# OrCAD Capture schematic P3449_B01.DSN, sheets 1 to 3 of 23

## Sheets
1 0022_Mechanical: size Custom
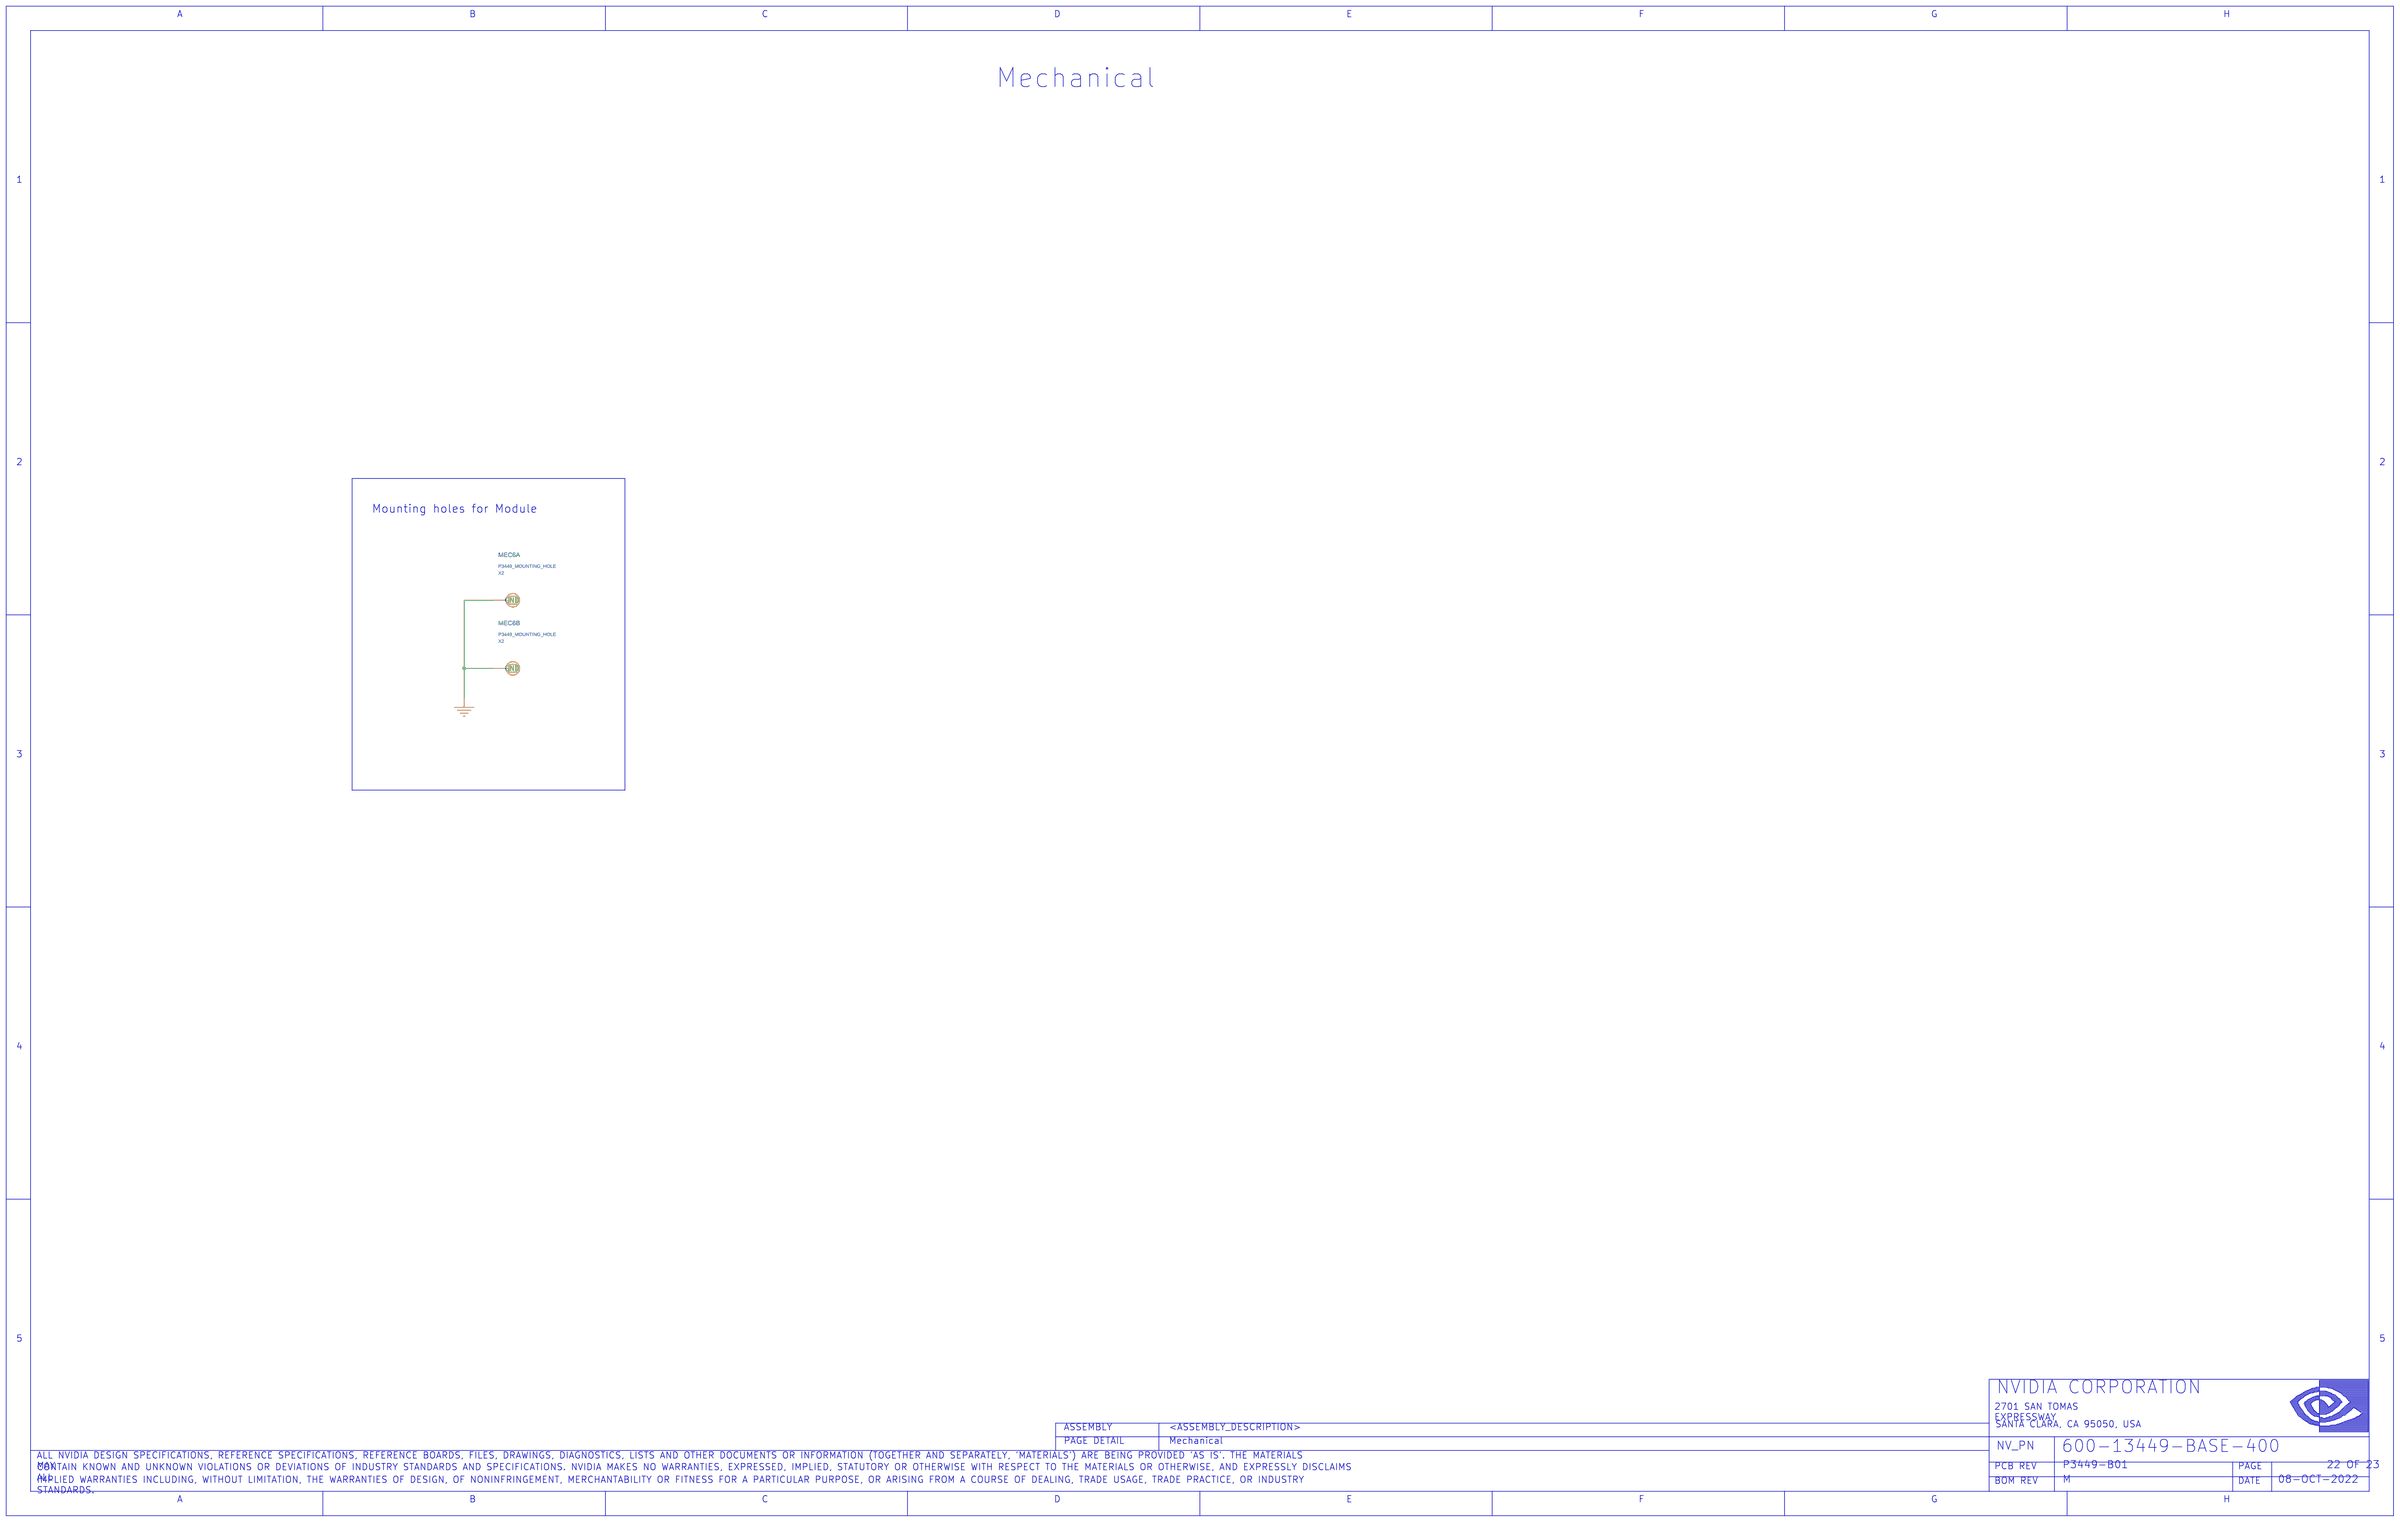
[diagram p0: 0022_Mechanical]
2 0021_Loop Back Test: size Custom
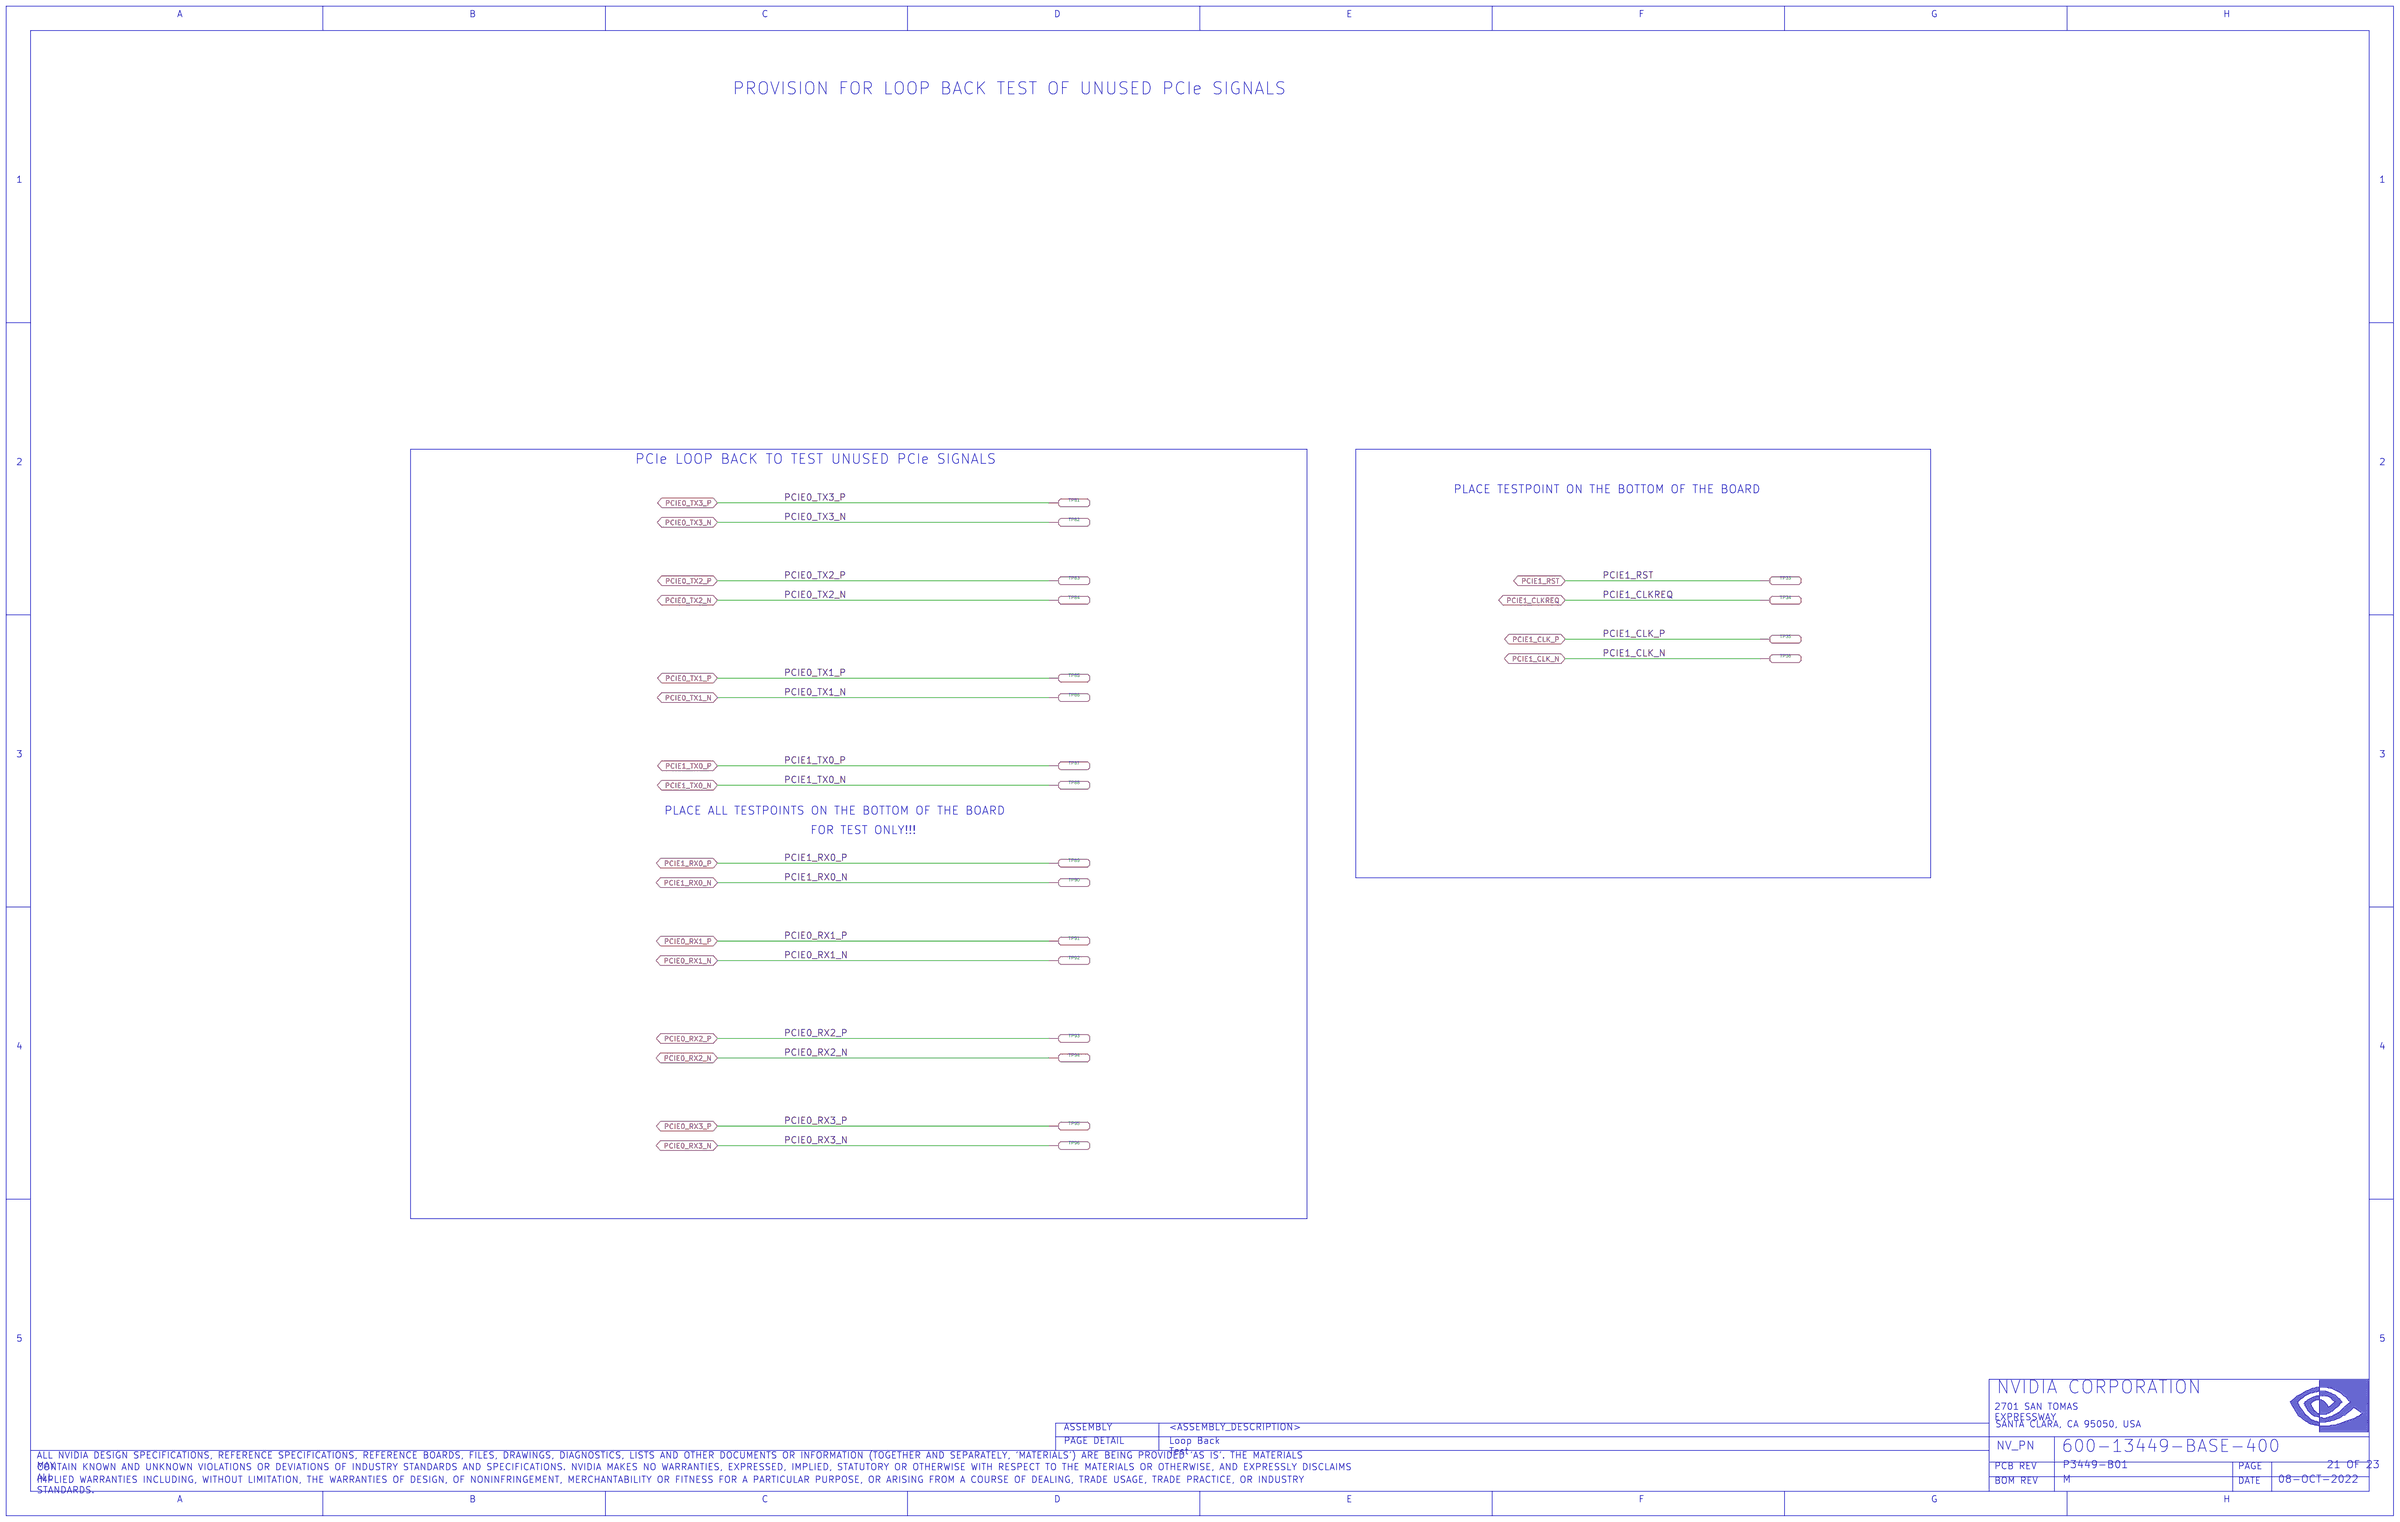
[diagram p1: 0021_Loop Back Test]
3 0020_Fan, Debug and EEPROM: size Custom
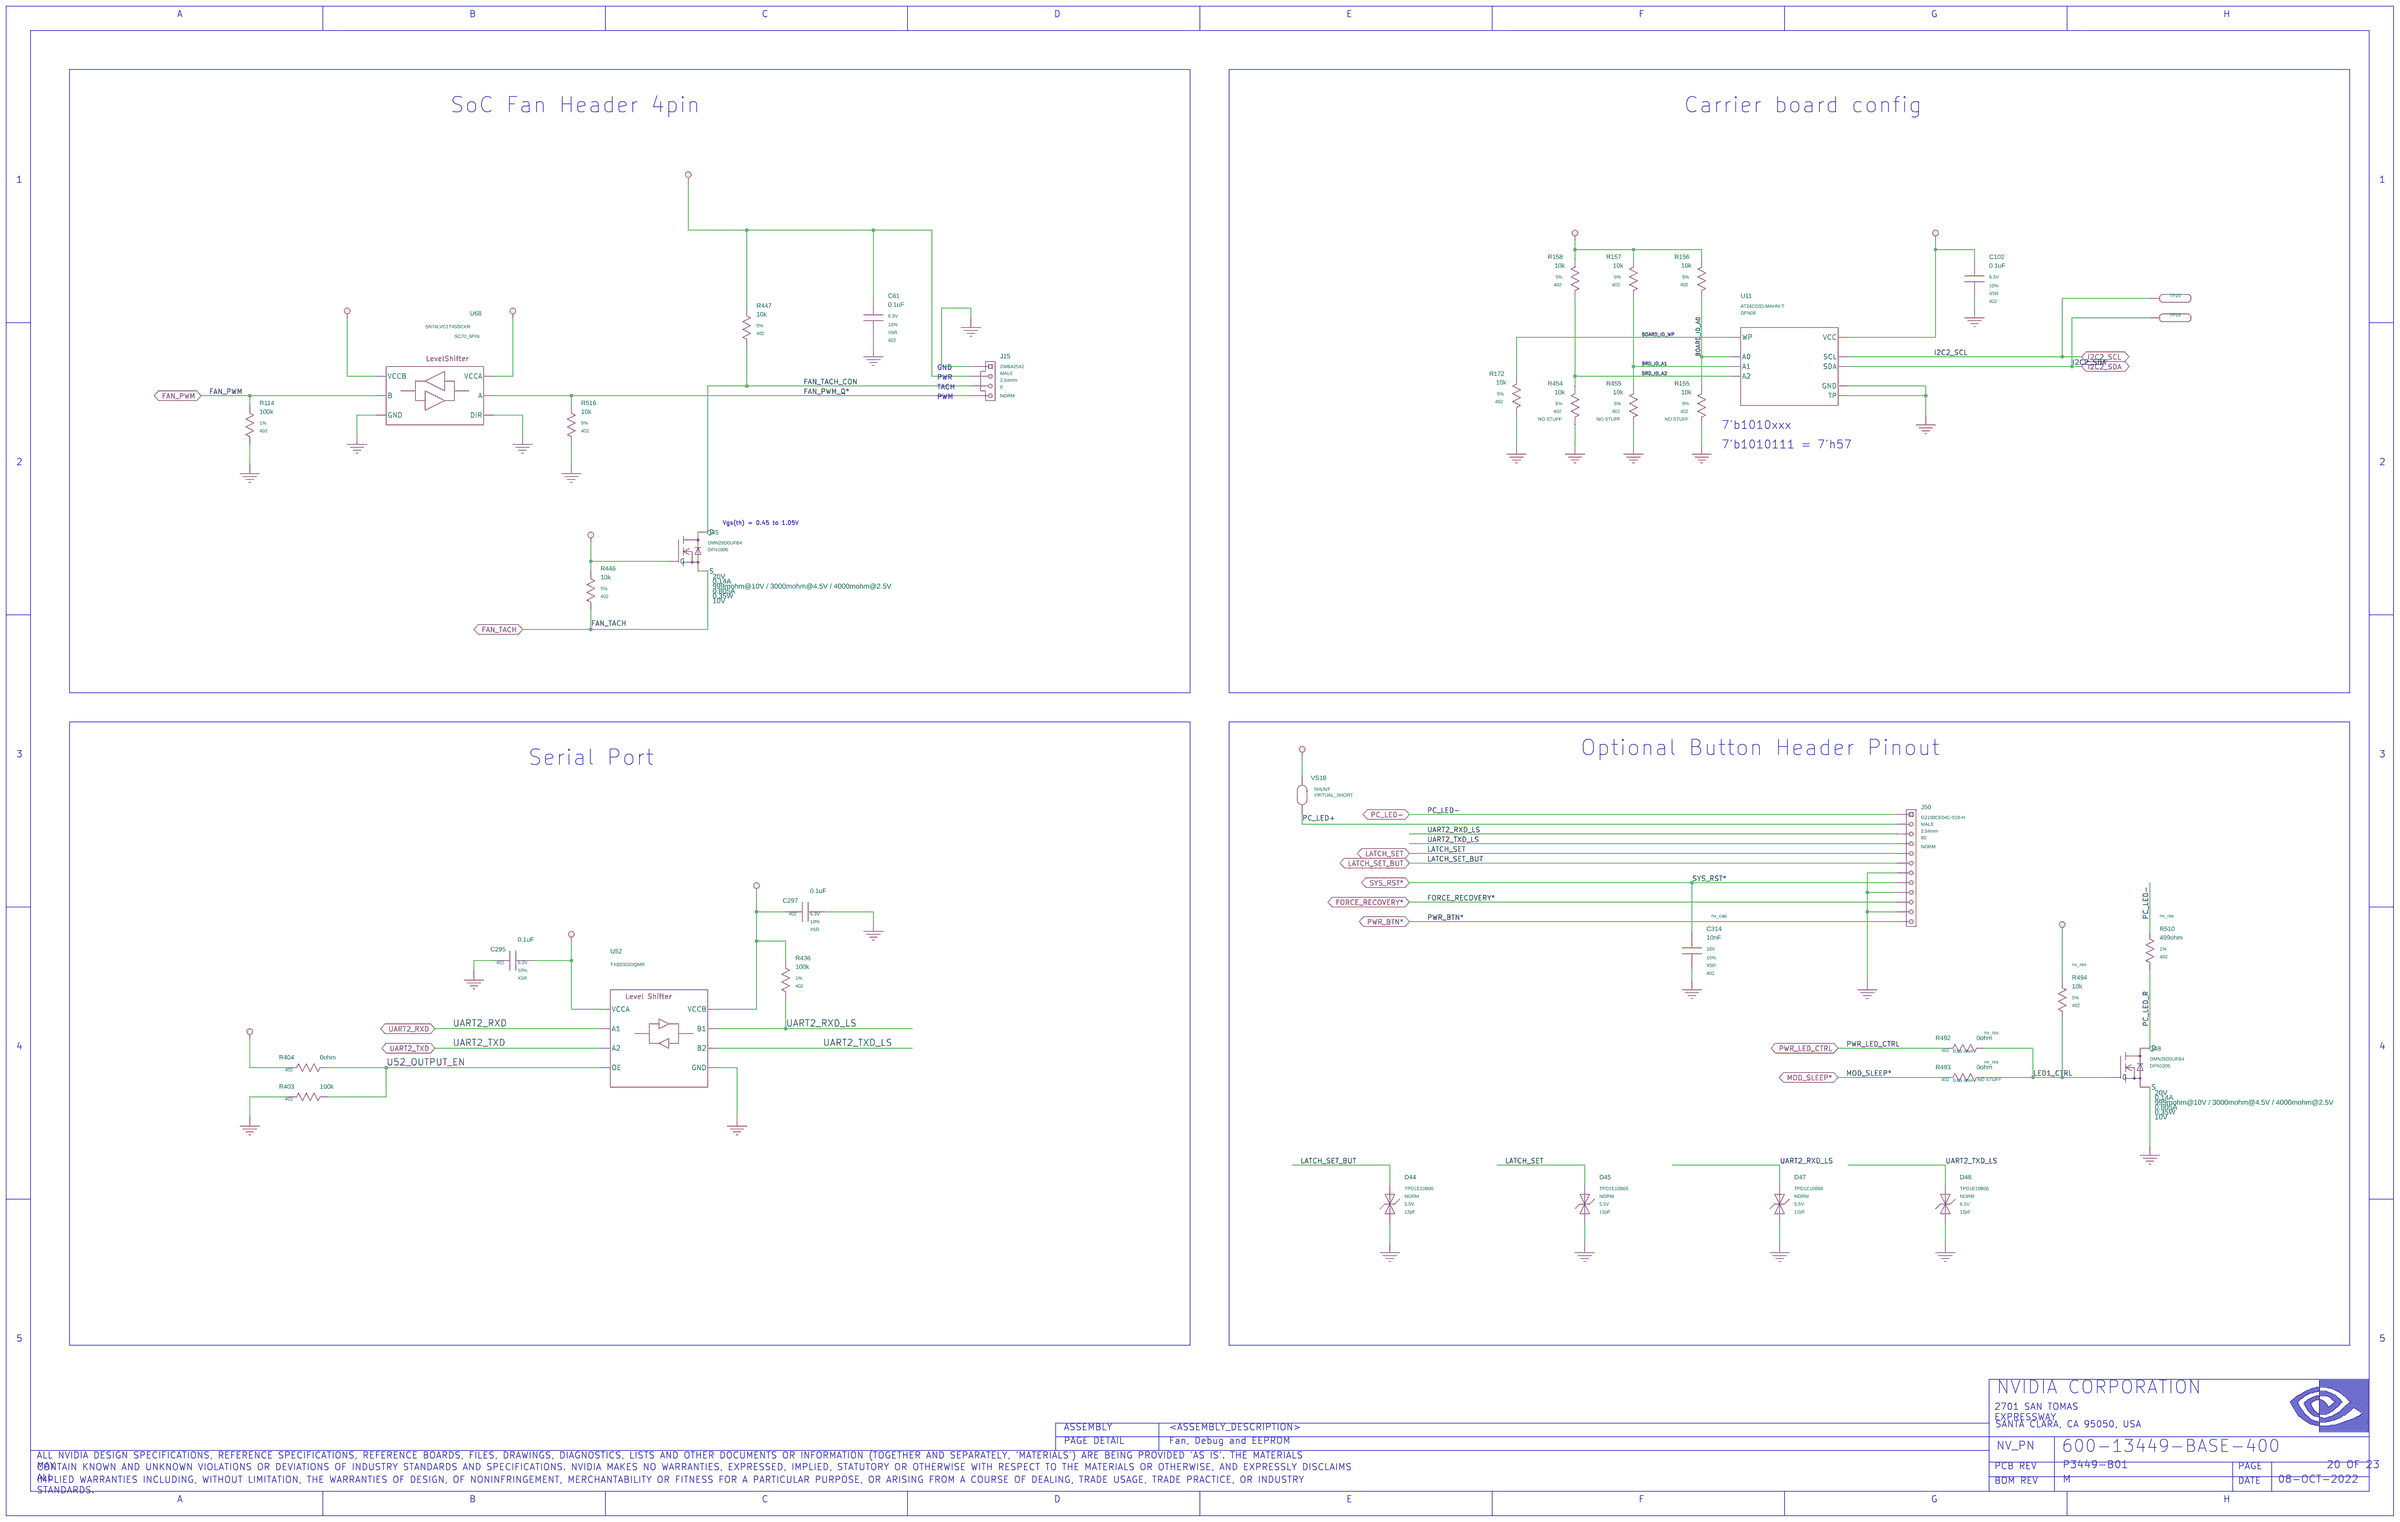
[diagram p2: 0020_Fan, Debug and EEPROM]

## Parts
sheet 0020_Fan, Debug and EEPROM
C61  0.1uF  [402]
C102  0.1uF  [402]
C295  0.1uF  [402]
C297  0.1uF  [402]
C314  10nF  [402]
D44  D_ESD  [DIODE_SMD_010X060]
D45  D_ESD  [DIODE_SMD_010X060]
D47  D_ESD  [DIODE_SMD_010X060]
D48  D_ESD  [DIODE_SMD_010X060]
J15  HDR_1X4  [CON_HDR_001X004_TH_ST_M_P025_B]
J50  HDR_1X12  [CON_HDR_001X012_TH_RA_M_P025]
Q45  Q_FET_N_ENH  [DFET_003_SMD_010X006_B]
Q48  Q_FET_N_ENH  [DFET_003_SMD_010X006_B]
R114  100k  [402]
R155  10k  [402]
R156  10k  [402]
R157  10k  [402]
R158  10k  [402]
R172  10k  [402]
R403  100k  [402]
R404  0ohm  [402]
R436  100k  [402]
R446  10k  [402]
R447  10k  [402]
R454  10k  [402]
R455  10k  [402]
R492  0ohm  [402]
R493  0ohm  [402]
R494  10k  [402]
R510  499ohm  [402]
R516  10k  [402]
TP19  LABTESTPOINT  [LTPB071C125D045C025P]
TP20  LABTESTPOINT  [LTPB071C125D045C025P]
U11  U_MEM_EE_I2C  [DFN08_P050_030X020_T016X016]
U52  U_LEVSHFT_TXB0302  [DFN08_P040_018X012]
U68  U_LEVSHFT_3STATE  [SC70_6]
VS18  VIRTUAL_SHORT  [VIRTUAL_SHORT]
sheet 0021_Loop Back Test
TP33  LABTESTPOINT  [LTPB071C125D045C025P]
TP34  LABTESTPOINT  [LTPB071C125D045C025P]
TP35  LABTESTPOINT  [LTPB071C125D045C025P]
TP36  LABTESTPOINT  [LTPB071C125D045C025P]
TP81  LABTESTPOINT  [LTPB071C125D045C025P]
TP82  LABTESTPOINT  [LTPB071C125D045C025P]
TP83  LABTESTPOINT  [LTPB071C125D045C025P]
TP84  LABTESTPOINT  [LTPB071C125D045C025P]
TP85  LABTESTPOINT  [LTPB071C125D045C025P]
TP86  LABTESTPOINT  [LTPB071C125D045C025P]
TP87  LABTESTPOINT  [LTPB071C125D045C025P]
TP88  LABTESTPOINT  [LTPB071C125D045C025P]
TP89  LABTESTPOINT  [LTPB071C125D045C025P]
TP90  LABTESTPOINT  [LTPB071C125D045C025P]
TP91  LABTESTPOINT  [LTPB071C125D045C025P]
TP92  LABTESTPOINT  [LTPB071C125D045C025P]
TP93  LABTESTPOINT  [LTPB071C125D045C025P]
TP94  LABTESTPOINT  [LTPB071C125D045C025P]
TP95  LABTESTPOINT  [LTPB071C125D045C025P]
TP96  LABTESTPOINT  [LTPB071C125D045C025P]
sheet 0022_Mechanical
MEC6  MOUNTING_HOLE  [MECH_RECT_01000X00790_HOLES]  (sections A,B)

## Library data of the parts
C61 = C#1: ASSEMBLY: FAN; CDS_LIB: discrete; CDS_PART_NAME: C_0402-0.1UF,X5R,10%,6.3V,039-0007-000; CDS_PHYS_PART_NAME: C_0402-0.1UF,X5R,10%,6.3V,039-0007-000-0.1UF,039-0007-000; CDS_SEC: 1; CHIPS_PART_NAME: C; DEVICE_TYPENAME: C_0402-01UFX5R1063V039-0007-000-01UF039-0007-000; DRAWING: @P3449_B01_LIB.P3449_B01(SCH_1):PAGE20; MAT: X5R; MAX_VOLTAGE: 6.3V; NV_PN: 039-0007-000; PATH: I22; PHYS_PAGE: 20; ROT: 0; SEC: 1; SIGNAL_MODEL: nv_cap; TOL: 10%; VER: 1; XY: (-7700,6000)
C102 = C#1: ASSEMBLY: L4T_EEPROM; CDS_LIB: discrete; CDS_PART_NAME: C_0402-0.1UF,X5R,10%,6.3V,039-0007-000; CDS_PHYS_PART_NAME: C_0402-0.1UF,X5R,10%,6.3V,039-0007-000-0.1UF,039-0007-000; CDS_SEC: 1; CHIPS_PART_NAME: C; DEVICE_TYPENAME: C_0402-01UFX5R1063V039-0007-000-01UF039-0007-000; DRAWING: @P3449_B01_LIB.P3449_B01(SCH_1):PAGE20; MAT: X5R; MAX_VOLTAGE: 6.3V; NV_PN: 039-0007-000; PATH: I341; PHYS_PAGE: 20; ROT: 0; SEC: 1; SIGNAL_MODEL: nv_cap; TOL: 10%; VER: 1; XY: (-2050,6200)
C295 = C: ASSEMBLY: DEBUG; CDS_LIB: discrete; CDS_PART_NAME: C_0402-0.1UF,X5R,10%,6.3V,039-0007-000; CDS_PHYS_PART_NAME: C_0402-0.1UF,X5R,10%,6.3V,039-0007-000-0.1UF,039-0007-000; CDS_SEC: 1; DEVICE_TYPENAME: C_0402-01UFX5R1063V039-0007-000-01UF039-0007-000; DRAWING: @P3449_B01_LIB.P3449_B01(SCH_1):PAGE20; MAT: X5R; MAX_VOLTAGE: 6.3V; NV_PN: 039-0007-000; PATH: I309; PHYS_PAGE: 20; ROT: 0; SEC: 1; SIGNAL_MODEL: nv_cap; TOL: 10%; VER: 2; XY: (-9550,2700)
C297 = C: ASSEMBLY: DEBUG; CDS_LIB: discrete; CDS_PART_NAME: C_0402-0.1UF,X5R,10%,6.3V,039-0007-000; CDS_PHYS_PART_NAME: C_0402-0.1UF,X5R,10%,6.3V,039-0007-000-0.1UF,039-0007-000; CDS_SEC: 1; DEVICE_TYPENAME: C_0402-01UFX5R1063V039-0007-000-01UF039-0007-000; DRAWING: @P3449_B01_LIB.P3449_B01(SCH_1):PAGE20; MAT: X5R; MAX_VOLTAGE: 6.3V; NV_PN: 039-0007-000; PATH: I307; PHYS_PAGE: 20; ROT: 0; SEC: 1; SIGNAL_MODEL: nv_cap; TOL: 10%; VER: 2; XY: (-8050,2950)
C314 = C#1: ASSEMBLY: AUTOMATION; CDS_LIB: discrete; CDS_PART_NAME: C_0402-10NF,X5R,10%,16V,039-0024-000; CDS_PHYS_PART_NAME: C_0402-10NF,X5R,10%,16V,039-0024-000-039-0024-000,10NF; CDS_SEC: 1; CHIPS_PART_NAME: C; DEVICE_TYPENAME: C_0402-10NFX5R1016V039-0024-000-039-0024-00010NF; DRAWING: @P3449_B01_LIB.P3449_B01(SCH_1):PAGE20; MAT: X5R; MAX_VOLTAGE: 16V; NV_PN: 039-0024-000; PATH: I402; PHYS_PAGE: 20; ROT: 0; SEC: 1; SIGNAL_MODEL: nv_cap; TOL: 10%; VER: 1; XY: (-3500,2750)
D44 = D_ESD: ASSEMBLY: AUTOMATION; BREAKDOWN_VOLTAGE_MIN_TYP: 6V; CAPACITANCE_MAX_TYP: 12pF; CDS_LIB: discrete; CDS_PART_NAME: D_ESD_NORM-TPD1E10B06,1 LINE,BI-DIRECTIONAL,5.5V,0.1UA,6V,10V@1A,12PF,090-0243-000; CDS_PHYS_PART_NAME: D_ESD_NORM-TPD1E10B06,1 LINE,BI-DIRECTIONAL,5.5V,0.1UA,6V,10V@1A,12PF,090-0243-000-090-0243-000; CDS_SEC: 1; CLAMPING_VOLTAGE: 10V@1A; CONFIGURATION: 1 Line; DEVICE_TYPENAME: D_ESD_NORM-TPD1E10B061LINEBI-DIRECTIONAL55V01UA6V10V1A12PF090-0243-000-090-0243-000; DRAWING: @P3449_B01_LIB.P3449_B01(SCH_1):PAGE20; MAX_REVERSE_LEAKAGE_CURRENT: 0.1uA; MAX_REVERSE_VOLTAGE: 5.5V; NV_NAME: TPD1E10B06; NV_PN: 090-0243-000; PACK_TYPE: NORM; PATH: I396; PHYS_PAGE: 20; POLARITY: Bi-Directional; ROT: 0; SEC: 1; VER: 2; XY: (-5050,1450)
D45 = D_ESD: ASSEMBLY: AUTOMATION; BREAKDOWN_VOLTAGE_MIN_TYP: 6V; CAPACITANCE_MAX_TYP: 12pF; CDS_LIB: discrete; CDS_PART_NAME: D_ESD_NORM-TPD1E10B06,1 LINE,BI-DIRECTIONAL,5.5V,0.1UA,6V,10V@1A,12PF,090-0243-000; CDS_PHYS_PART_NAME: D_ESD_NORM-TPD1E10B06,1 LINE,BI-DIRECTIONAL,5.5V,0.1UA,6V,10V@1A,12PF,090-0243-000-090-0243-000; CDS_SEC: 1; CLAMPING_VOLTAGE: 10V@1A; CONFIGURATION: 1 Line; DEVICE_TYPENAME: D_ESD_NORM-TPD1E10B061LINEBI-DIRECTIONAL55V01UA6V10V1A12PF090-0243-000-090-0243-000; DRAWING: @P3449_B01_LIB.P3449_B01(SCH_1):PAGE20; MAX_REVERSE_LEAKAGE_CURRENT: 0.1uA; MAX_REVERSE_VOLTAGE: 5.5V; NV_NAME: TPD1E10B06; NV_PN: 090-0243-000; PACK_TYPE: NORM; PATH: I399; PHYS_PAGE: 20; POLARITY: Bi-Directional; ROT: 0; SEC: 1; VER: 2; XY: (-4050,1450)
D47 = D_ESD: ASSEMBLY: AUTOMATION; BREAKDOWN_VOLTAGE_MIN_TYP: 6V; CAPACITANCE_MAX_TYP: 12pF; CDS_LIB: discrete; CDS_PART_NAME: D_ESD_NORM-TPD1E10B06,1 LINE,BI-DIRECTIONAL,5.5V,0.1UA,6V,10V@1A,12PF,090-0243-000; CDS_PHYS_PART_NAME: D_ESD_NORM-TPD1E10B06,1 LINE,BI-DIRECTIONAL,5.5V,0.1UA,6V,10V@1A,12PF,090-0243-000-090-0243-000; CDS_SEC: 1; CLAMPING_VOLTAGE: 10V@1A; CONFIGURATION: 1 Line; DEVICE_TYPENAME: D_ESD_NORM-TPD1E10B061LINEBI-DIRECTIONAL55V01UA6V10V1A12PF090-0243-000-090-0243-000; DRAWING: @P3449_B01_LIB.P3449_B01(SCH_1):PAGE20; MAX_REVERSE_LEAKAGE_CURRENT: 0.1uA; MAX_REVERSE_VOLTAGE: 5.5V; NV_NAME: TPD1E10B06; NV_PN: 090-0243-000; PACK_TYPE: NORM; PATH: I392; PHYS_PAGE: 20; POLARITY: Bi-Directional; ROT: 0; SEC: 1; VER: 2; XY: (-3050,1450)
D48 = D_ESD: ASSEMBLY: AUTOMATION; BREAKDOWN_VOLTAGE_MIN_TYP: 6V; CAPACITANCE_MAX_TYP: 12pF; CDS_LIB: discrete; CDS_PART_NAME: D_ESD_NORM-TPD1E10B06,1 LINE,BI-DIRECTIONAL,5.5V,0.1UA,6V,10V@1A,12PF,090-0243-000; CDS_PHYS_PART_NAME: D_ESD_NORM-TPD1E10B06,1 LINE,BI-DIRECTIONAL,5.5V,0.1UA,6V,10V@1A,12PF,090-0243-000-090-0243-000; CDS_SEC: 1; CLAMPING_VOLTAGE: 10V@1A; CONFIGURATION: 1 Line; DEVICE_TYPENAME: D_ESD_NORM-TPD1E10B061LINEBI-DIRECTIONAL55V01UA6V10V1A12PF090-0243-000-090-0243-000; DRAWING: @P3449_B01_LIB.P3449_B01(SCH_1):PAGE20; MAX_REVERSE_LEAKAGE_CURRENT: 0.1uA; MAX_REVERSE_VOLTAGE: 5.5V; NV_NAME: TPD1E10B06; NV_PN: 090-0243-000; PACK_TYPE: NORM; PATH: I393; PHYS_PAGE: 20; POLARITY: Bi-Directional; ROT: 0; SEC: 1; VER: 2; XY: (-2200,1450)
J15 = HDR_1X4: ANGLE: 0; ASSEMBLY: FAN; CDS_LIB: electro_mechanic; CDS_PART_NAME: HDR_1X4_NORM-2WBA2542,MALE,2.54MM,0,NO,NO,YES,250 V,4 A,064-0400-000; CDS_PHYS_PART_NAME: HDR_1X4_NORM-2WBA2542,MALE,2.54MM,0,NO,NO,YES,250 V,4 A,064-0400-000-064-0400-000; CDS_SEC: 1; DEVICE_TYPENAME: HDR_1X4_NORM-2WBA2542MALE254MM0NONOYES250V4A064-0400-000-064-0400-000; DRAWING: @P3449_B01_LIB.P3449_B01(SCH_1):PAGE20; GENDER: MALE; LATCHING: YES; MAX_CURRENT: 4:00 上午; MAX_VOLTAGE: 250 V; NV_NAME: 2WBA2542; NV_PN: 064-0400-000; PACK_TYPE: NORM; PATH: I368; PHYS_PAGE: 20; PITCH: 2.54mm; REFLOW: NO; ROT: 0; SEC: 1; SEC_TYPE: NORM; SHROUDED: NO; VER: 1; XY: (-7100,5750)
J50 = HDR_1X12: ANGLE: 90; ASSEMBLY: AUTOMATION; CDS_LIB: electro_mechanic; CDS_PART_NAME: HDR_1X12_NORM-G2100CE04C-016-H,MALE,2.54MM,90,YES,NO,NO,125 V,3 A,074-0239-000; CDS_PHYS_PART_NAME: HDR_1X12_NORM-G2100CE04C-016-H,MALE,2.54MM,90,YES,NO,NO,125 V,3 A,074-0239-000-074-0239-000; CDS_SEC: 1; DEVICE_TYPENAME: HDR_1X12_NORM-G2100CE04C-016-HMALE254MM90YESNONO125V3A074-0239-000-074-0239-000; DRAWING: @P3449_B01_LIB.P3449_B01(SCH_1):PAGE20; GENDER: MALE; LATCHING: NO; MAX_CURRENT: 3:00 上午; MAX_VOLTAGE: 125 V; NV_NAME: G2100CE04C-016-H; NV_PN: 074-0239-000; PACK_TYPE: NORM; PATH: I425; PHYS_PAGE: 20; PITCH: 2.54mm; REFLOW: YES; ROT: 0; SEC: 1; SHROUDED: NO; VER: 1; XY: (-2400,3200)
Q45 = Q_FET_N_ENH#1: ASSEMBLY: FAN; CDS_LIB: discrete; CDS_PART_NAME: Q_FET_N_ENH_DFN1006-DMN26D0UFB4,20V,999MOHM@10V / 3000MOHM@4.5V / 4000MOHM@2.5V,0.14A,0.805A,10V,0.35W,999NC@10V / 0NC@4.5V / A; CDS_PHYS_PART_NAME: Q_FET_N_ENH_DFN1006-DMN26D0UFB4,20V,999MOHM@10V / 3000MOHM@4.5V / 4000MOHM@2.5V,0.14A,0.805A,10V,0.35W,999NC@10V / 0NC@4.5V / B; CDS_SEC: 1; CONTINUOUS_CURRENT: 0.14A; CaptureCellPackProp: Q_FET_N_ENH##1; DEVICE_TYPENAME: Q_FET_N_ENH_DFN1006-DMN26D0UFB420V999MOHM10V3000MOHM45V4000MOHM25V014A0805A10V035W999NC10V0NC45VB; DRAWING: @P3449_B01_LIB.P3449_B01(SCH_1):PAGE20; MAX_CURRENT: 0.805A; MAX_VOLTAGE: 20V; MAX_WATTAGE: 0.35W; NV_NAME: DMN26D0UFB4; NV_PN: 300-0868-000; PACK_TYPE: DFN1006; PATH: I369; PHYS_PAGE: 20; Q_G: 999nC@10V / 0nC@4.5V / 999nC@2.5V; ROT: 0; R_DS_ON: 999mohm@10V / 3000mohm@4.5V / 4000mohm@2.5V; SEC: 1; VER: 2; V_BE_GS: 10V; XY: (-8650,4800)
Q48 = Q_FET_N_ENH#1: ASSEMBLY: AUTOMATION; CDS_LIB: discrete; CDS_PART_NAME: Q_FET_N_ENH_DFN1006-DMN26D0UFB4,20V,999MOHM@10V / 3000MOHM@4.5V / 4000MOHM@2.5V,0.14A,0.805A,10V,0.35W,999NC@10V / 0NC@4.5V / A; CDS_PHYS_PART_NAME: Q_FET_N_ENH_DFN1006-DMN26D0UFB4,20V,999MOHM@10V / 3000MOHM@4.5V / 4000MOHM@2.5V,0.14A,0.805A,10V,0.35W,999NC@10V / 0NC@4.5V / B; CDS_SEC: 1; CONTINUOUS_CURRENT: 0.14A; CaptureCellPackProp: Q_FET_N_ENH##1; DEVICE_TYPENAME: Q_FET_N_ENH_DFN1006-DMN26D0UFB420V999MOHM10V3000MOHM45V4000MOHM25V014A0805A10V035W999NC10V0NC45VB; DRAWING: @P3449_B01_LIB.P3449_B01(SCH_1):PAGE20; MAX_CURRENT: 0.805A; MAX_VOLTAGE: 20V; MAX_WATTAGE: 0.35W; NV_NAME: DMN26D0UFB4; NV_PN: 300-0868-000; PACK_TYPE: DFN1006; PATH: I419; PHYS_PAGE: 20; Q_G: 999nC@10V / 0nC@4.5V / 999nC@2.5V; ROT: 0; R_DS_ON: 999mohm@10V / 3000mohm@4.5V / 4000mohm@2.5V; SEC: 1; VER: 2; V_BE_GS: 10V; XY: (-1250,2150)
R114 = R: ASSEMBLY: FAN; CDS_LIB: discrete; CDS_PART_NAME: R_0402-100K,1 %,62.5MW,195-0005-000; CDS_PHYS_PART_NAME: R_0402-100K,1 %,62.5MW,195-0005-000-100K,195-0005-000; CDS_SEC: 1; DEVICE_TYPENAME: R_0402-100K1625MW195-0005-000-100K195-0005-000; DRAWING: @P3449_B01_LIB.P3449_B01(SCH_1):PAGE20; MAX_WATTAGE: 62.5mW; NV_PN: 195-0005-000; PATH: I3; PHYS_PAGE: 20; ROT: 0; SEC: 1; SIGNAL_MODEL: nv_res; TOL: 1%; VER: 2; XY: (-10900,5450)
R155 = R: ASSEMBLY: L4T_EEPROM; CDS_LIB: discrete; CDS_PART_NAME: R_0402-10K,5 %,62.5MW,195-0486-000; CDS_PHYS_PART_NAME: R_0402-10K,5 %,62.5MW,195-0486-000-10K,195-0486-000; CDS_SEC: 1; DEVICE_TYPENAME: R_0402-10K5625MW195-0486-000-10K195-0486-000; DRAWING: @P3449_B01_LIB.P3449_B01(SCH_1):PAGE20; MAX_WATTAGE: 62.5mW; NV_PN: 195-0486-000; PATH: I348; PHYS_PAGE: 20; ROT: 2; SEC: 1; SIGNAL_MODEL: nv_res; SKU: NO STUFF; TOL: 5%; VER: 2; XY: (-3450,5550)
R156 = R: ASSEMBLY: L4T_EEPROM; CDS_LIB: discrete; CDS_PART_NAME: R_0402-10K,5 %,62.5MW,195-0486-000; CDS_PHYS_PART_NAME: R_0402-10K,5 %,62.5MW,195-0486-000-10K,195-0486-000; CDS_SEC: 1; DEVICE_TYPENAME: R_0402-10K5625MW195-0486-000-10K195-0486-000; DRAWING: @P3449_B01_LIB.P3449_B01(SCH_1):PAGE20; MAX_WATTAGE: 62.5mW; NV_PN: 195-0486-000; PATH: I343; PHYS_PAGE: 20; ROT: 2; SEC: 1; SIGNAL_MODEL: nv_res; TOL: 5%; VER: 2; XY: (-3450,6200)
R157 = R: ASSEMBLY: L4T_EEPROM; CDS_LIB: discrete; CDS_PART_NAME: R_0402-10K,5 %,62.5MW,195-0486-000; CDS_PHYS_PART_NAME: R_0402-10K,5 %,62.5MW,195-0486-000-10K,195-0486-000; CDS_SEC: 1; DEVICE_TYPENAME: R_0402-10K5625MW195-0486-000-10K195-0486-000; DRAWING: @P3449_B01_LIB.P3449_B01(SCH_1):PAGE20; MAX_WATTAGE: 62.5mW; NV_PN: 195-0486-000; PATH: I344; PHYS_PAGE: 20; ROT: 2; SEC: 1; SIGNAL_MODEL: nv_res; TOL: 5%; VER: 2; XY: (-3800,6200)
R158 = R: ASSEMBLY: L4T_EEPROM; CDS_LIB: discrete; CDS_PART_NAME: R_0402-10K,5 %,62.5MW,195-0486-000; CDS_PHYS_PART_NAME: R_0402-10K,5 %,62.5MW,195-0486-000-10K,195-0486-000; CDS_SEC: 1; DEVICE_TYPENAME: R_0402-10K5625MW195-0486-000-10K195-0486-000; DRAWING: @P3449_B01_LIB.P3449_B01(SCH_1):PAGE20; MAX_WATTAGE: 62.5mW; NV_PN: 195-0486-000; PATH: I346; PHYS_PAGE: 20; ROT: 2; SEC: 1; SIGNAL_MODEL: nv_res; TOL: 5%; VER: 2; XY: (-4100,6200)
R172 = R: ASSEMBLY: L4T_EEPROM; CDS_LIB: discrete; CDS_PART_NAME: R_0402-10K,5 %,62.5MW,195-0486-000; CDS_PHYS_PART_NAME: R_0402-10K,5 %,62.5MW,195-0486-000-10K,195-0486-000; CDS_SEC: 1; DEVICE_TYPENAME: R_0402-10K5625MW195-0486-000-10K195-0486-000; DRAWING: @P3449_B01_LIB.P3449_B01(SCH_1):PAGE20; MAX_WATTAGE: 62.5mW; NV_PN: 195-0486-000; PATH: I350; PHYS_PAGE: 20; ROT: 2; SEC: 1; SIGNAL_MODEL: nv_res; TOL: 5%; VER: 2; XY: (-4400,5600)
R403 = R#1: ASSEMBLY: DEBUG; CDS_LIB: discrete; CDS_PART_NAME: R_0402-100K,1 %,62.5MW,195-0005-000; CDS_PHYS_PART_NAME: R_0402-100K,1 %,62.5MW,195-0005-000-100K,195-0005-000; CDS_SEC: 1; CHIPS_PART_NAME: R; DEVICE_TYPENAME: R_0402-100K1625MW195-0005-000-100K195-0005-000; DRAWING: @P3449_B01_LIB.P3449_B01(SCH_1):PAGE20; MAX_WATTAGE: 62.5mW; NV_PN: 195-0005-000; PATH: I317; PHYS_PAGE: 20; ROT: 0; SEC: 1; SIGNAL_MODEL: nv_res; TOL: 1%; VER: 1; XY: (-10600,2000)
R404 = R#1: ASSEMBLY: DEBUG; CDS_LIB: discrete; CDS_PART_NAME: R_0402-0OHM,0.05 OHM,62.5MW,195-2655-000; CDS_PHYS_PART_NAME: R_0402-0OHM,0.05 OHM,62.5MW,195-2655-000-0OHM,195-2655-000; CDS_SEC: 1; CHIPS_PART_NAME: R; DEVICE_TYPENAME: R_0402-0OHM005OHM625MW195-2655-000-0OHM195-2655-000; DRAWING: @P3449_B01_LIB.P3449_B01(SCH_1):PAGE20; MAX_WATTAGE: 62.5mW; NV_PN: 195-2655-000; PATH: I318; PHYS_PAGE: 20; ROT: 0; SEC: 1; SIGNAL_MODEL: nv_res; TOL: 0.05 ohm; VER: 1; XY: (-10600,2150)
R436 = R: ASSEMBLY: DEBUG; CDS_LIB: discrete; CDS_PART_NAME: R_0402-100K,1 %,62.5MW,195-0005-000; CDS_PHYS_PART_NAME: R_0402-100K,1 %,62.5MW,195-0005-000-100K,195-0005-000; CDS_SEC: 1; DEVICE_TYPENAME: R_0402-100K1625MW195-0005-000-100K195-0005-000; DRAWING: @P3449_B01_LIB.P3449_B01(SCH_1):PAGE20; MAX_WATTAGE: 62.5mW; NV_PN: 195-0005-000; PATH: I367; PHYS_PAGE: 20; ROT: 0; SEC: 1; SIGNAL_MODEL: nv_res; TOL: 1%; VER: 2; XY: (-8150,2600)
R446 = R: ASSEMBLY: FAN; CDS_LIB: discrete; CDS_PART_NAME: R_0402-10K,5 %,62.5MW,195-0486-000; CDS_PHYS_PART_NAME: R_0402-10K,5 %,62.5MW,195-0486-000-10K,195-0486-000; CDS_SEC: 1; DEVICE_TYPENAME: R_0402-10K5625MW195-0486-000-10K195-0486-000; DRAWING: @P3449_B01_LIB.P3449_B01(SCH_1):PAGE20; MAX_WATTAGE: 62.5mW; NV_PN: 195-0486-000; PATH: I370; PHYS_PAGE: 20; ROT: 0; SEC: 1; SIGNAL_MODEL: nv_res; TOL: 5%; VER: 2; XY: (-9150,4600)
R447 = R: ASSEMBLY: FAN; CDS_LIB: discrete; CDS_PART_NAME: R_0402-10K,5 %,62.5MW,195-0486-000; CDS_PHYS_PART_NAME: R_0402-10K,5 %,62.5MW,195-0486-000-10K,195-0486-000; CDS_SEC: 1; DEVICE_TYPENAME: R_0402-10K5625MW195-0486-000-10K195-0486-000; DRAWING: @P3449_B01_LIB.P3449_B01(SCH_1):PAGE20; MAX_WATTAGE: 62.5mW; NV_PN: 195-0486-000; PATH: I372; PHYS_PAGE: 20; ROT: 0; SEC: 1; SIGNAL_MODEL: nv_res; TOL: 5%; VER: 2; XY: (-8350,5950)
R454 = R: ASSEMBLY: L4T_EEPROM; CDS_LIB: discrete; CDS_PART_NAME: R_0402-10K,5 %,62.5MW,195-0486-000; CDS_PHYS_PART_NAME: R_0402-10K,5 %,62.5MW,195-0486-000-10K,195-0486-000; CDS_SEC: 1; DEVICE_TYPENAME: R_0402-10K5625MW195-0486-000-10K195-0486-000; DRAWING: @P3449_B01_LIB.P3449_B01(SCH_1):PAGE20; MAX_WATTAGE: 62.5mW; NV_PN: 195-0486-000; PATH: I375; PHYS_PAGE: 20; ROT: 2; SEC: 1; SIGNAL_MODEL: nv_res; SKU: NO STUFF; TOL: 5%; VER: 2; XY: (-4100,5550)
R455 = R: ASSEMBLY: L4T_EEPROM; CDS_LIB: discrete; CDS_PART_NAME: R_0402-10K,5 %,62.5MW,195-0486-000; CDS_PHYS_PART_NAME: R_0402-10K,5 %,62.5MW,195-0486-000-10K,195-0486-000; CDS_SEC: 1; DEVICE_TYPENAME: R_0402-10K5625MW195-0486-000-10K195-0486-000; DRAWING: @P3449_B01_LIB.P3449_B01(SCH_1):PAGE20; MAX_WATTAGE: 62.5mW; NV_PN: 195-0486-000; PATH: I374; PHYS_PAGE: 20; ROT: 2; SEC: 1; SIGNAL_MODEL: nv_res; SKU: NO STUFF; TOL: 5%; VER: 2; XY: (-3800,5550)
R492 = R#1: ASSEMBLY: AUTOMATION; CDS_LIB: discrete; CDS_PART_NAME: R_0402-0OHM,0.05 OHM,62.5MW,195-2655-000; CDS_PHYS_PART_NAME: R_0402-0OHM,0.05 OHM,62.5MW,195-2655-000-0OHM,195-2655-000; CDS_SEC: 1; CHIPS_PART_NAME: R; DEVICE_TYPENAME: R_0402-0OHM005OHM625MW195-2655-000-0OHM195-2655-000; DRAWING: @P3449_B01_LIB.P3449_B01(SCH_1):PAGE20; MAX_WATTAGE: 62.5mW; NV_PN: 195-2655-000; PATH: I426; PHYS_PAGE: 20; ROT: 0; SEC: 1; SIGNAL_MODEL: nv_res; TOL: 0.05 ohm; VER: 1; XY: (-2100,2250)
R493 = R#1: ASSEMBLY: AUTOMATION; CDS_LIB: discrete; CDS_PART_NAME: R_0402-0OHM,0.05 OHM,62.5MW,195-2655-000; CDS_PHYS_PART_NAME: R_0402-0OHM,0.05 OHM,62.5MW,195-2655-000-0OHM,195-2655-000; CDS_SEC: 1; CHIPS_PART_NAME: R; DEVICE_TYPENAME: R_0402-0OHM005OHM625MW195-2655-000-0OHM195-2655-000; DRAWING: @P3449_B01_LIB.P3449_B01(SCH_1):PAGE20; MAX_WATTAGE: 62.5mW; NV_PN: 195-2655-000; PATH: I427; PHYS_PAGE: 20; ROT: 0; SEC: 1; SIGNAL_MODEL: nv_res; SKU: NO STUFF; TOL: 0.05 ohm; VER: 1; XY: (-2100,2100)
R494 = R: ASSEMBLY: AUTOMATION; CDS_LIB: discrete; CDS_PART_NAME: R_0402-10K,5 %,62.5MW,195-0486-000; CDS_PHYS_PART_NAME: R_0402-10K,5 %,62.5MW,195-0486-000-10K,195-0486-000; CDS_SEC: 1; DEVICE_TYPENAME: R_0402-10K5625MW195-0486-000-10K195-0486-000; DRAWING: @P3449_B01_LIB.P3449_B01(SCH_1):PAGE20; MAX_WATTAGE: 62.5mW; NV_PN: 195-0486-000; PATH: I430; PHYS_PAGE: 20; ROT: 0; SEC: 1; SIGNAL_MODEL: nv_res; TOL: 5%; VER: 2; XY: (-1600,2500)
R510 = R: ASSEMBLY: AUTOMATION; CDS_LIB: discrete; CDS_PART_NAME: R_0402-499OHM,1 %,62.5MW,195-0338-000; CDS_PHYS_PART_NAME: R_0402-499OHM,1 %,62.5MW,195-0338-000-195-0338-000,499OHM; CDS_SEC: 1; DEVICE_TYPENAME: R_0402-499OHM1625MW195-0338-000-195-0338-000499OHM; DRAWING: @P3449_B01_LIB.P3449_B01(SCH_1):PAGE20; MAX_WATTAGE: 62.5mW; NV_PN: 195-0338-000; PATH: I420; PHYS_PAGE: 20; ROT: 0; SEC: 1; SIGNAL_MODEL: nv_res; TOL: 1%; VER: 2; XY: (-1150,2750)
R516 = R: ASSEMBLY: FAN; CDS_LIB: discrete; CDS_PART_NAME: R_0402-100K,1 %,62.5MW,195-0005-000; CDS_PHYS_PART_NAME: R_0402-100K,1 %,62.5MW,195-0005-000-100K,195-0005-000; CDS_SEC: 1; DEVICE_TYPENAME: R_0402-100K1625MW195-0005-000-100K195-0005-000; DRAWING: @P3449_B01_LIB.P3449_B01(SCH_1):PAGE20; MAX_WATTAGE: 62.5mW; NV_PN: 195-0005-000; PATH: I439; PHYS_PAGE: 20; ROT: 0; SEC: 1; SIGNAL_MODEL: nv_res; TOL: 5%; VER: 2; XY: (-9250,5450)
TP19 = LABTESTPOINT#1: CDS_LIB: electro_mechanic; CDS_PART_NAME: LABTESTPOINT_PIN-LTPB071C125; CDS_PHYS_PART_NAME: LABTESTPOINT_PIN-LTPB071C125; CDS_SEC: 1; DEVICE_TYPENAME: LABTESTPOINT_PIN-LTPB071C125; DRAWING: @P3449_B01_LIB.P3449_B01(SCH_1):PAGE20; NV_NAME: LTPB071C125; PACK_TYPE: PIN; PATH: I337; PHYS_PAGE: 20; ROT: 0; SEC: 1; VER: 3; XY: (-1100,6000)
TP20 = LABTESTPOINT#1: CDS_LIB: electro_mechanic; CDS_PART_NAME: LABTESTPOINT_PIN-LTPB071C125; CDS_PHYS_PART_NAME: LABTESTPOINT_PIN-LTPB071C125; CDS_SEC: 1; DEVICE_TYPENAME: LABTESTPOINT_PIN-LTPB071C125; DRAWING: @P3449_B01_LIB.P3449_B01(SCH_1):PAGE20; NV_NAME: LTPB071C125; PACK_TYPE: PIN; PATH: I336; PHYS_PAGE: 20; ROT: 0; SEC: 1; VER: 3; XY: (-1100,6100)
U11 = U_MEM_EE_I2C: ASSEMBLY: L4T_EEPROM; CDS_LIB: memory; CDS_PART_NAME: U_MEM_EE_I2C_DFN08-1MHZ,1.7V..3.6V,AT24C02D-MAHM-T,174-0159-000; CDS_PHYS_PART_NAME: U_MEM_EE_I2C_DFN08-1MHZ,1.7V..3.6V,AT24C02D-MAHM-T,174-0159-000-174-0159-000; CDS_SEC: 1; DEVICE_TYPENAME: U_MEM_EE_I2C_DFN08-1MHZ17V36VAT24C02D-MAHM-T174-0159-000-174-0159-000; DRAWING: @P3449_B01_LIB.P3449_B01(SCH_1):PAGE20; NV_NAME: AT24C02D-MAHM-T; NV_PN: 174-0159-000; PACK_TYPE: DFN08; PATH: I335; PHYS_PAGE: 20; POW: 1.7V..3.6V; ROT: 0; SEC: 1; SEC_TYPE: DFN08; SPEED_GRADE: 1MHz; VER: 2; XY: (-3000,5750)
U52 = U_LEVSHFT_TXB0302: ASSEMBLY: DEBUG; CDS_LIB: logic; CDS_PART_NAME: U_LEVSHFT_TXB0302_DFN8-TXB0302DQMR,LEVEL SHIFTER,115-2177-000; CDS_PHYS_PART_NAME: U_LEVSHFT_TXB0302_DFN8-TXB0302DQMR,LEVEL SHIFTER,115-2177-000-115-2177-000; CDS_SEC: 1; DEVICE_TYPENAME: U_LEVSHFT_TXB0302_DFN8-TXB0302DQMRLEVELSHIFTER115-2177-000-115-2177-000; DRAWING: @P3449_B01_LIB.P3449_B01(SCH_1):PAGE20; FUNCTION: Level Shifter; NV_NAME: TXB0302DQMR; NV_PN: 115-2177-000; PATH: I365; PHYS_PAGE: 20; ROT: 0; SEC: 1; VER: 1; XY: (-8800,2300)
U68 = U_LEVSHFT_3STATE: ASSEMBLY: FAN; CDS_LIB: logic; CDS_PART_NAME: U_LEVSHFT_3STATE_SC70_6PIN-SN74LVC1T45DCKR-P,LEVEL SHIFTER,115-1968-000; CDS_PHYS_PART_NAME: U_LEVSHFT_3STATE_SC70_6PIN-SN74LVC1T45DCKR-P,LEVEL SHIFTER,115-1968-000-115-1968-000; CDS_SEC: 1; DEVICE_TYPENAME: U_LEVSHFT_3STATE_SC70_6PIN-SN74LVC1T45DCKR-PLEVELSHIFTER115-1968-000-115-1968-000; DRAWING: @P3449_B01_LIB.P3449_B01(SCH_1):PAGE20; FUNCTION: Level Shifter; NV_NAME: SN74LVC1T45DCKR; NV_PN: 115-1968-000; PACK_TYPE: SC70_6PIN; PATH: I435; PHYS_PAGE: 20; ROT: 2; SEC: 1; VER: 1; XY: (-9950,5600)
VS18 = VIRTUAL_SHORT#1: CDS_LIB: mechanic; CDS_PART_NAME: VIRTUAL_SHORT_SHUNT-VIRTUAL_SHORT; CDS_PHYS_PART_NAME: VIRTUAL_SHORT_SHUNT-VIRTUAL_SHORT; CDS_SEC: 1; DEVICE_TYPENAME: VIRTUAL_SHORT_SHUNT-VIRTUAL_SHORT; DRAWING: @P3449_B01_LIB.P3449_B01(SCH_1):PAGE20; PACK_TYPE: SHUNT; PATH: I424; PHYS_PAGE: 20; ROT: 0; SEC: 1; VER: 2; XY: (-5500,3550)
TP33 = LABTESTPOINT#1: CDS_LIB: electro_mechanic; CDS_PART_NAME: LABTESTPOINT_PIN-LTPB071C125; CDS_PHYS_PART_NAME: LABTESTPOINT_PIN-LTPB071C125; CDS_SEC: 1; DEVICE_TYPENAME: LABTESTPOINT_PIN-LTPB071C125; DRAWING: @P3449_B01_LIB.P3449_B01(SCH_1):PAGE21; NV_NAME: LTPB071C125; PACK_TYPE: PIN; PATH: I80; PHYS_PAGE: 21; ROT: 0; SEC: 1; VER: 3; XY: (-3100,4650)
TP34 = LABTESTPOINT#1: CDS_LIB: electro_mechanic; CDS_PART_NAME: LABTESTPOINT_PIN-LTPB071C125; CDS_PHYS_PART_NAME: LABTESTPOINT_PIN-LTPB071C125; CDS_SEC: 1; DEVICE_TYPENAME: LABTESTPOINT_PIN-LTPB071C125; DRAWING: @P3449_B01_LIB.P3449_B01(SCH_1):PAGE21; NV_NAME: LTPB071C125; PACK_TYPE: PIN; PATH: I85; PHYS_PAGE: 21; ROT: 0; SEC: 1; VER: 3; XY: (-3100,4550)
TP35 = LABTESTPOINT#1: CDS_LIB: electro_mechanic; CDS_PART_NAME: LABTESTPOINT_PIN-LTPB071C125; CDS_PHYS_PART_NAME: LABTESTPOINT_PIN-LTPB071C125; CDS_SEC: 1; DEVICE_TYPENAME: LABTESTPOINT_PIN-LTPB071C125; DRAWING: @P3449_B01_LIB.P3449_B01(SCH_1):PAGE21; NV_NAME: LTPB071C125; PACK_TYPE: PIN; PATH: I86; PHYS_PAGE: 21; ROT: 0; SEC: 1; VER: 3; XY: (-3100,4350)
TP36 = LABTESTPOINT#1: CDS_LIB: electro_mechanic; CDS_PART_NAME: LABTESTPOINT_PIN-LTPB071C125; CDS_PHYS_PART_NAME: LABTESTPOINT_PIN-LTPB071C125; CDS_SEC: 1; DEVICE_TYPENAME: LABTESTPOINT_PIN-LTPB071C125; DRAWING: @P3449_B01_LIB.P3449_B01(SCH_1):PAGE21; NV_NAME: LTPB071C125; PACK_TYPE: PIN; PATH: I87; PHYS_PAGE: 21; ROT: 0; SEC: 1; VER: 3; XY: (-3100,4250)
TP81 = LABTESTPOINT#1: CDS_LIB: electro_mechanic; CDS_PART_NAME: LABTESTPOINT_PIN-LTPB071C125; CDS_PHYS_PART_NAME: LABTESTPOINT_PIN-LTPB071C125; CDS_SEC: 1; DEVICE_TYPENAME: LABTESTPOINT_PIN-LTPB071C125; DRAWING: @P3449_B01_LIB.P3449_B01(SCH_1):PAGE21; NV_NAME: LTPB071C125; PACK_TYPE: PIN; PATH: I111; PHYS_PAGE: 21; ROT: 0; SEC: 1; VER: 3; XY: (-6750,5050)
TP82 = LABTESTPOINT#1: CDS_LIB: electro_mechanic; CDS_PART_NAME: LABTESTPOINT_PIN-LTPB071C125; CDS_PHYS_PART_NAME: LABTESTPOINT_PIN-LTPB071C125; CDS_SEC: 1; DEVICE_TYPENAME: LABTESTPOINT_PIN-LTPB071C125; DRAWING: @P3449_B01_LIB.P3449_B01(SCH_1):PAGE21; NV_NAME: LTPB071C125; PACK_TYPE: PIN; PATH: I110; PHYS_PAGE: 21; ROT: 0; SEC: 1; VER: 3; XY: (-6750,4950)
TP83 = LABTESTPOINT#1: CDS_LIB: electro_mechanic; CDS_PART_NAME: LABTESTPOINT_PIN-LTPB071C125; CDS_PHYS_PART_NAME: LABTESTPOINT_PIN-LTPB071C125; CDS_SEC: 1; DEVICE_TYPENAME: LABTESTPOINT_PIN-LTPB071C125; DRAWING: @P3449_B01_LIB.P3449_B01(SCH_1):PAGE21; NV_NAME: LTPB071C125; PACK_TYPE: PIN; PATH: I109; PHYS_PAGE: 21; ROT: 0; SEC: 1; VER: 3; XY: (-6750,4650)
TP84 = LABTESTPOINT#1: CDS_LIB: electro_mechanic; CDS_PART_NAME: LABTESTPOINT_PIN-LTPB071C125; CDS_PHYS_PART_NAME: LABTESTPOINT_PIN-LTPB071C125; CDS_SEC: 1; DEVICE_TYPENAME: LABTESTPOINT_PIN-LTPB071C125; DRAWING: @P3449_B01_LIB.P3449_B01(SCH_1):PAGE21; NV_NAME: LTPB071C125; PACK_TYPE: PIN; PATH: I108; PHYS_PAGE: 21; ROT: 0; SEC: 1; VER: 3; XY: (-6750,4550)
TP85 = LABTESTPOINT#1: CDS_LIB: electro_mechanic; CDS_PART_NAME: LABTESTPOINT_PIN-LTPB071C125; CDS_PHYS_PART_NAME: LABTESTPOINT_PIN-LTPB071C125; CDS_SEC: 1; DEVICE_TYPENAME: LABTESTPOINT_PIN-LTPB071C125; DRAWING: @P3449_B01_LIB.P3449_B01(SCH_1):PAGE21; NV_NAME: LTPB071C125; PACK_TYPE: PIN; PATH: I107; PHYS_PAGE: 21; ROT: 0; SEC: 1; VER: 3; XY: (-6750,4150)
TP86 = LABTESTPOINT#1: CDS_LIB: electro_mechanic; CDS_PART_NAME: LABTESTPOINT_PIN-LTPB071C125; CDS_PHYS_PART_NAME: LABTESTPOINT_PIN-LTPB071C125; CDS_SEC: 1; DEVICE_TYPENAME: LABTESTPOINT_PIN-LTPB071C125; DRAWING: @P3449_B01_LIB.P3449_B01(SCH_1):PAGE21; NV_NAME: LTPB071C125; PACK_TYPE: PIN; PATH: I106; PHYS_PAGE: 21; ROT: 0; SEC: 1; VER: 3; XY: (-6750,4050)
TP87 = LABTESTPOINT#1: CDS_LIB: electro_mechanic; CDS_PART_NAME: LABTESTPOINT_PIN-LTPB071C125; CDS_PHYS_PART_NAME: LABTESTPOINT_PIN-LTPB071C125; CDS_SEC: 1; DEVICE_TYPENAME: LABTESTPOINT_PIN-LTPB071C125; DRAWING: @P3449_B01_LIB.P3449_B01(SCH_1):PAGE21; NV_NAME: LTPB071C125; PACK_TYPE: PIN; PATH: I105; PHYS_PAGE: 21; ROT: 0; SEC: 1; VER: 3; XY: (-6750,3700)
TP88 = LABTESTPOINT#1: CDS_LIB: electro_mechanic; CDS_PART_NAME: LABTESTPOINT_PIN-LTPB071C125; CDS_PHYS_PART_NAME: LABTESTPOINT_PIN-LTPB071C125; CDS_SEC: 1; DEVICE_TYPENAME: LABTESTPOINT_PIN-LTPB071C125; DRAWING: @P3449_B01_LIB.P3449_B01(SCH_1):PAGE21; NV_NAME: LTPB071C125; PACK_TYPE: PIN; PATH: I104; PHYS_PAGE: 21; ROT: 0; SEC: 1; VER: 3; XY: (-6750,3600)
TP89 = LABTESTPOINT#1: CDS_LIB: electro_mechanic; CDS_PART_NAME: LABTESTPOINT_PIN-LTPB071C125; CDS_PHYS_PART_NAME: LABTESTPOINT_PIN-LTPB071C125; CDS_SEC: 1; DEVICE_TYPENAME: LABTESTPOINT_PIN-LTPB071C125; DRAWING: @P3449_B01_LIB.P3449_B01(SCH_1):PAGE21; NV_NAME: LTPB071C125; PACK_TYPE: PIN; PATH: I96; PHYS_PAGE: 21; ROT: 0; SEC: 1; VER: 3; XY: (-6750,3200)
TP90 = LABTESTPOINT#1: CDS_LIB: electro_mechanic; CDS_PART_NAME: LABTESTPOINT_PIN-LTPB071C125; CDS_PHYS_PART_NAME: LABTESTPOINT_PIN-LTPB071C125; CDS_SEC: 1; DEVICE_TYPENAME: LABTESTPOINT_PIN-LTPB071C125; DRAWING: @P3449_B01_LIB.P3449_B01(SCH_1):PAGE21; NV_NAME: LTPB071C125; PACK_TYPE: PIN; PATH: I97; PHYS_PAGE: 21; ROT: 0; SEC: 1; VER: 3; XY: (-6750,3100)
TP91 = LABTESTPOINT#1: CDS_LIB: electro_mechanic; CDS_PART_NAME: LABTESTPOINT_PIN-LTPB071C125; CDS_PHYS_PART_NAME: LABTESTPOINT_PIN-LTPB071C125; CDS_SEC: 1; DEVICE_TYPENAME: LABTESTPOINT_PIN-LTPB071C125; DRAWING: @P3449_B01_LIB.P3449_B01(SCH_1):PAGE21; NV_NAME: LTPB071C125; PACK_TYPE: PIN; PATH: I98; PHYS_PAGE: 21; ROT: 0; SEC: 1; VER: 3; XY: (-6750,2800)
TP92 = LABTESTPOINT#1: CDS_LIB: electro_mechanic; CDS_PART_NAME: LABTESTPOINT_PIN-LTPB071C125; CDS_PHYS_PART_NAME: LABTESTPOINT_PIN-LTPB071C125; CDS_SEC: 1; DEVICE_TYPENAME: LABTESTPOINT_PIN-LTPB071C125; DRAWING: @P3449_B01_LIB.P3449_B01(SCH_1):PAGE21; NV_NAME: LTPB071C125; PACK_TYPE: PIN; PATH: I99; PHYS_PAGE: 21; ROT: 0; SEC: 1; VER: 3; XY: (-6750,2700)
TP93 = LABTESTPOINT#1: CDS_LIB: electro_mechanic; CDS_PART_NAME: LABTESTPOINT_PIN-LTPB071C125; CDS_PHYS_PART_NAME: LABTESTPOINT_PIN-LTPB071C125; CDS_SEC: 1; DEVICE_TYPENAME: LABTESTPOINT_PIN-LTPB071C125; DRAWING: @P3449_B01_LIB.P3449_B01(SCH_1):PAGE21; NV_NAME: LTPB071C125; PACK_TYPE: PIN; PATH: I100; PHYS_PAGE: 21; ROT: 0; SEC: 1; VER: 3; XY: (-6750,2300)
TP94 = LABTESTPOINT#1: CDS_LIB: electro_mechanic; CDS_PART_NAME: LABTESTPOINT_PIN-LTPB071C125; CDS_PHYS_PART_NAME: LABTESTPOINT_PIN-LTPB071C125; CDS_SEC: 1; DEVICE_TYPENAME: LABTESTPOINT_PIN-LTPB071C125; DRAWING: @P3449_B01_LIB.P3449_B01(SCH_1):PAGE21; NV_NAME: LTPB071C125; PACK_TYPE: PIN; PATH: I101; PHYS_PAGE: 21; ROT: 0; SEC: 1; VER: 3; XY: (-6750,2200)
TP95 = LABTESTPOINT#1: CDS_LIB: electro_mechanic; CDS_PART_NAME: LABTESTPOINT_PIN-LTPB071C125; CDS_PHYS_PART_NAME: LABTESTPOINT_PIN-LTPB071C125; CDS_SEC: 1; DEVICE_TYPENAME: LABTESTPOINT_PIN-LTPB071C125; DRAWING: @P3449_B01_LIB.P3449_B01(SCH_1):PAGE21; NV_NAME: LTPB071C125; PACK_TYPE: PIN; PATH: I102; PHYS_PAGE: 21; ROT: 0; SEC: 1; VER: 3; XY: (-6750,1850)
TP96 = LABTESTPOINT#1: CDS_LIB: electro_mechanic; CDS_PART_NAME: LABTESTPOINT_PIN-LTPB071C125; CDS_PHYS_PART_NAME: LABTESTPOINT_PIN-LTPB071C125; CDS_SEC: 1; DEVICE_TYPENAME: LABTESTPOINT_PIN-LTPB071C125; DRAWING: @P3449_B01_LIB.P3449_B01(SCH_1):PAGE21; NV_NAME: LTPB071C125; PACK_TYPE: PIN; PATH: I103; PHYS_PAGE: 21; ROT: 0; SEC: 1; VER: 3; XY: (-6750,1750)
MEC6 = MOUNTING_HOLE: CDS_LIB: mechanic; CDS_PART_NAME: MOUNTING_HOLE_X2-P3449_MOUNTING_HOLE; CDS_PHYS_PART_NAME: MOUNTING_HOLE_X2-P3449_MOUNTING_HOLE; CDS_SEC: 2; DEVICE_TYPENAME: MOUNTING_HOLE_X2-P3449_MOUNTING_HOLE; DRAWING: @P3449_B01_LIB.P3449_B01(SCH_1):PAGE22; NV_NAME: P3449_MOUNTING_HOLE; PACK_TYPE: X2; PATH: I2; PHYS_PAGE: 22; ROT: 0; SEC: 2; VER: 1; XY: (-9550,4200)

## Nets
GND: C61.2 C102.2 C295.1 C297.2 C314.2 D44.2 D45.2 D47.2 D48.2 J15.1 J50.7 J50.9 J50.11 MEC6.1(GND) MEC6.2(GND) Q48.2(S) R114.2 R155.2 R172.2 R403.1 R454.2 R455.2 R516.2 U11.4(GND) U11.9(TP) U52.4(GND) U68.2(GND) U68.5(DIR) ; also on sheet 4 5 6 7 8 9 10 11 12 13 14 15 16 19
VDD_1V8: C102.1 C295.2 Q45.1(G) R156.1 R157.1 R158.1 R404.1 R446.1 R494.1 U11.8(VCC) U52.1(VCCA) U68.6(VCCB) ; also on sheet 4 6 7 9 11 19
VDD_3V3_SYS: C297.1 R436.1 U52.8(VCCB) ; also on sheet 4 5 6 7 8 9 11 18 19
VDD_5V_IN: C61.1 J15.2 R447.1 U68.1(VCCA) VS18.1(A) ; also on sheet 4 7 10 11 12 14 15 19
BOARD_ID_A0: R155.1 R156.2 U11.1(A0)
BOARD_ID_WP: R172.1 U11.7(WP)
BRD_ID_A1: R157.2 R455.1 U11.2(A1)
BRD_ID_A2: R158.2 R454.1 U11.3(A2)
FAN_PWM: R114.1 U68.4(B) ; also on sheet 18
FAN_PWM_Q*: J15.4 R516.1 U68.3(A)
FAN_TACH: Q45.2(S) R446.2 ; also on sheet 18
FAN_TACH_CON: J15.3 Q45.3(D) R447.2
FORCE_RECOVERY*: J50.10 ; also on sheet 19
I2C2_SCL: TP20.1 U11.6(SCL) ; also on sheet 9 19
I2C2_SDA: TP19.1 U11.5(SDA) ; also on sheet 9 19
LATCH_SET: D45.1 J50.5 ; also on sheet 10
LATCH_SET_BUT: D44.1 J50.6 ; also on sheet 10
LED1_CTRL: Q48.1(G) R492.2 R493.2 R494.2
MOD_SLEEP*: R493.1 ; also on sheet 7 19
PC_LED+: J50.2 VS18.2(B)
PC_LED-: J50.1 R510.1
PC_LED_R: Q48.3(D) R510.2
PCIE0_RX1_N: TP92.1 ; also on sheet 17
PCIE0_RX1_P: TP91.1 ; also on sheet 17
PCIE0_RX2_N: TP94.1 ; also on sheet 17
PCIE0_RX2_P: TP93.1 ; also on sheet 17
PCIE0_RX3_N: TP96.1 ; also on sheet 17
PCIE0_RX3_P: TP95.1 ; also on sheet 17
PCIE0_TX1_N: TP86.1 ; also on sheet 17
PCIE0_TX1_P: TP85.1 ; also on sheet 17
PCIE0_TX2_N: TP84.1 ; also on sheet 17
PCIE0_TX2_P: TP83.1 ; also on sheet 17
PCIE0_TX3_N: TP82.1 ; also on sheet 17
PCIE0_TX3_P: TP81.1 ; also on sheet 17
PCIE1_CLK_N: TP36.1 ; also on sheet 17
PCIE1_CLK_P: TP35.1 ; also on sheet 17
PCIE1_CLKREQ: TP34.1 ; also on sheet 17
PCIE1_RST: TP33.1 ; also on sheet 17
PCIE1_RX0_N: TP90.1 ; also on sheet 17
PCIE1_RX0_P: TP89.1 ; also on sheet 17
PCIE1_TX0_N: TP88.1 ; also on sheet 17
PCIE1_TX0_P: TP87.1 ; also on sheet 17
PWR_BTN*: J50.12 ; also on sheet 10 19
PWR_LED_CTRL: R492.1 ; also on sheet 18 19
SYS_RST*: C314.1 J50.8 ; also on sheet 11 19
U52_OUTPUT_EN: R403.2 R404.2 U52.5(OE)
UART2_RXD: U52.2(A1) ; also on sheet 19
UART2_RXD_LS: D47.1 J50.3 R436.2 U52.7(B1)
UART2_TXD: U52.3(A2) ; also on sheet 19
UART2_TXD_LS: D48.1 J50.4 U52.6(B2)

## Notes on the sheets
sheet 1
- A
- B
- C
- D
- E
- F
- G
- H
- Mechanical
- 1
- 1
- 2
- 2
- Mounting holes for Module
- 3
- 3
- 4
- 4
- 5
- 5
- NVIDIA CORPORATION
- 2701 SAN TOMAS
  EXPRESSWAY
- ASSEMBLY
- <ASSEMBLY_DESCRIPTION>
- SANTA CLARA, CA 95050, USA
- PAGE DETAIL
- Mechanical
- NV_PN
- 600-13449-BASE-400
- ALL NVIDIA DESIGN SPECIFICATIONS, REFERENCE SPECIFICATIONS, REFERENCE BOARDS, FILES, DRAWINGS, DIAGNOSTICS, LISTS AND OTHER DOCUMENTS OR INFORMATION (TOGETHER AND SEPARATELY, 'MATERIALS') ARE BEING PROVIDED 'AS IS'. THE MATERIALS
  MAY
- CONTAIN KNOWN AND UNKNOWN VIOLATIONS OR DEVIATIONS OF INDUSTRY STANDARDS AND SPECIFICATIONS. NVIDIA MAKES NO WARRANTIES, EXPRESSED, IMPLIED, STATUTORY OR OTHERWISE WITH RESPECT TO THE MATERIALS OR OTHERWISE, AND EXPRESSLY DISCLAIMS
  ALL
- PCB REV
- P3449-B01
- PAGE
- 22 OF 23
- IMPLIED WARRANTIES INCLUDING, WITHOUT LIMITATION, THE WARRANTIES OF DESIGN, OF NONINFRINGEMENT, MERCHANTABILITY OR FITNESS FOR A PARTICULAR PURPOSE, OR ARISING FROM A COURSE OF DEALING, TRADE USAGE, TRADE PRACTICE, OR INDUSTRY
  STANDARDS.
- BOM REV
- M
- DATE
- 08-OCT-2022
- A
- B
- C
- D
- E
- F
- G
- H
sheet 2
- A
- B
- C
- D
- E
- F
- G
- H
- PROVISION FOR LOOP BACK TEST OF UNUSED PCIe SIGNALS
- 1
- 1
- 2
- PCIe LOOP BACK TO TEST UNUSED PCIe SIGNALS
- 2
- PLACE TESTPOINT ON THE BOTTOM OF THE BOARD
- 3
- 3
- PLACE ALL TESTPOINTS ON THE BOTTOM OF THE BOARD
- FOR TEST ONLY!!!
- 4
- 4
- 5
- 5
- NVIDIA CORPORATION
- 2701 SAN TOMAS
  EXPRESSWAY
- ASSEMBLY
- <ASSEMBLY_DESCRIPTION>
- SANTA CLARA, CA 95050, USA
- PAGE DETAIL
- Loop Back
  Test
- NV_PN
- 600-13449-BASE-400
- ALL NVIDIA DESIGN SPECIFICATIONS, REFERENCE SPECIFICATIONS, REFERENCE BOARDS, FILES, DRAWINGS, DIAGNOSTICS, LISTS AND OTHER DOCUMENTS OR INFORMATION (TOGETHER AND SEPARATELY, 'MATERIALS') ARE BEING PROVIDED 'AS IS'. THE MATERIALS
  MAY
- CONTAIN KNOWN AND UNKNOWN VIOLATIONS OR DEVIATIONS OF INDUSTRY STANDARDS AND SPECIFICATIONS. NVIDIA MAKES NO WARRANTIES, EXPRESSED, IMPLIED, STATUTORY OR OTHERWISE WITH RESPECT TO THE MATERIALS OR OTHERWISE, AND EXPRESSLY DISCLAIMS
  ALL
- PCB REV
- P3449-B01
- PAGE
- 21 OF 23
- IMPLIED WARRANTIES INCLUDING, WITHOUT LIMITATION, THE WARRANTIES OF DESIGN, OF NONINFRINGEMENT, MERCHANTABILITY OR FITNESS FOR A PARTICULAR PURPOSE, OR ARISING FROM A COURSE OF DEALING, TRADE USAGE, TRADE PRACTICE, OR INDUSTRY
  STANDARDS.
- BOM REV
- M
- DATE
- 08-OCT-2022
- A
- B
- C
- D
- E
- F
- G
- H
sheet 3
- A
- B
- C
- D
- E
- F
- G
- H
- SoC Fan Header 4pin
- Carrier board config
- 1
- 1
- GND
- PWR
- TACH
- PWM
- 7'b1010xxx
- 7'b1010111 = 7'h57
- 2
- 2
- Vgs(th) = 0.45 to 1.05V
- Optional Button Header Pinout
- 3
- Serial Port
- 3
- 4
- 4
- 5
- 5
- NVIDIA CORPORATION
- 2701 SAN TOMAS
  EXPRESSWAY
- ASSEMBLY
- <ASSEMBLY_DESCRIPTION>
- SANTA CLARA, CA 95050, USA
- PAGE DETAIL
- Fan, Debug and EEPROM
- NV_PN
- 600-13449-BASE-400
- ALL NVIDIA DESIGN SPECIFICATIONS, REFERENCE SPECIFICATIONS, REFERENCE BOARDS, FILES, DRAWINGS, DIAGNOSTICS, LISTS AND OTHER DOCUMENTS OR INFORMATION (TOGETHER AND SEPARATELY, 'MATERIALS') ARE BEING PROVIDED 'AS IS'. THE MATERIALS
  MAY
- CONTAIN KNOWN AND UNKNOWN VIOLATIONS OR DEVIATIONS OF INDUSTRY STANDARDS AND SPECIFICATIONS. NVIDIA MAKES NO WARRANTIES, EXPRESSED, IMPLIED, STATUTORY OR OTHERWISE WITH RESPECT TO THE MATERIALS OR OTHERWISE, AND EXPRESSLY DISCLAIMS
  ALL
- PCB REV
- P3449-B01
- PAGE
- 20 OF 23
- IMPLIED WARRANTIES INCLUDING, WITHOUT LIMITATION, THE WARRANTIES OF DESIGN, OF NONINFRINGEMENT, MERCHANTABILITY OR FITNESS FOR A PARTICULAR PURPOSE, OR ARISING FROM A COURSE OF DEALING, TRADE USAGE, TRADE PRACTICE, OR INDUSTRY
  STANDARDS.
- BOM REV
- M
- DATE
- 08-OCT-2022
- A
- B
- C
- D
- E
- F
- G
- H
